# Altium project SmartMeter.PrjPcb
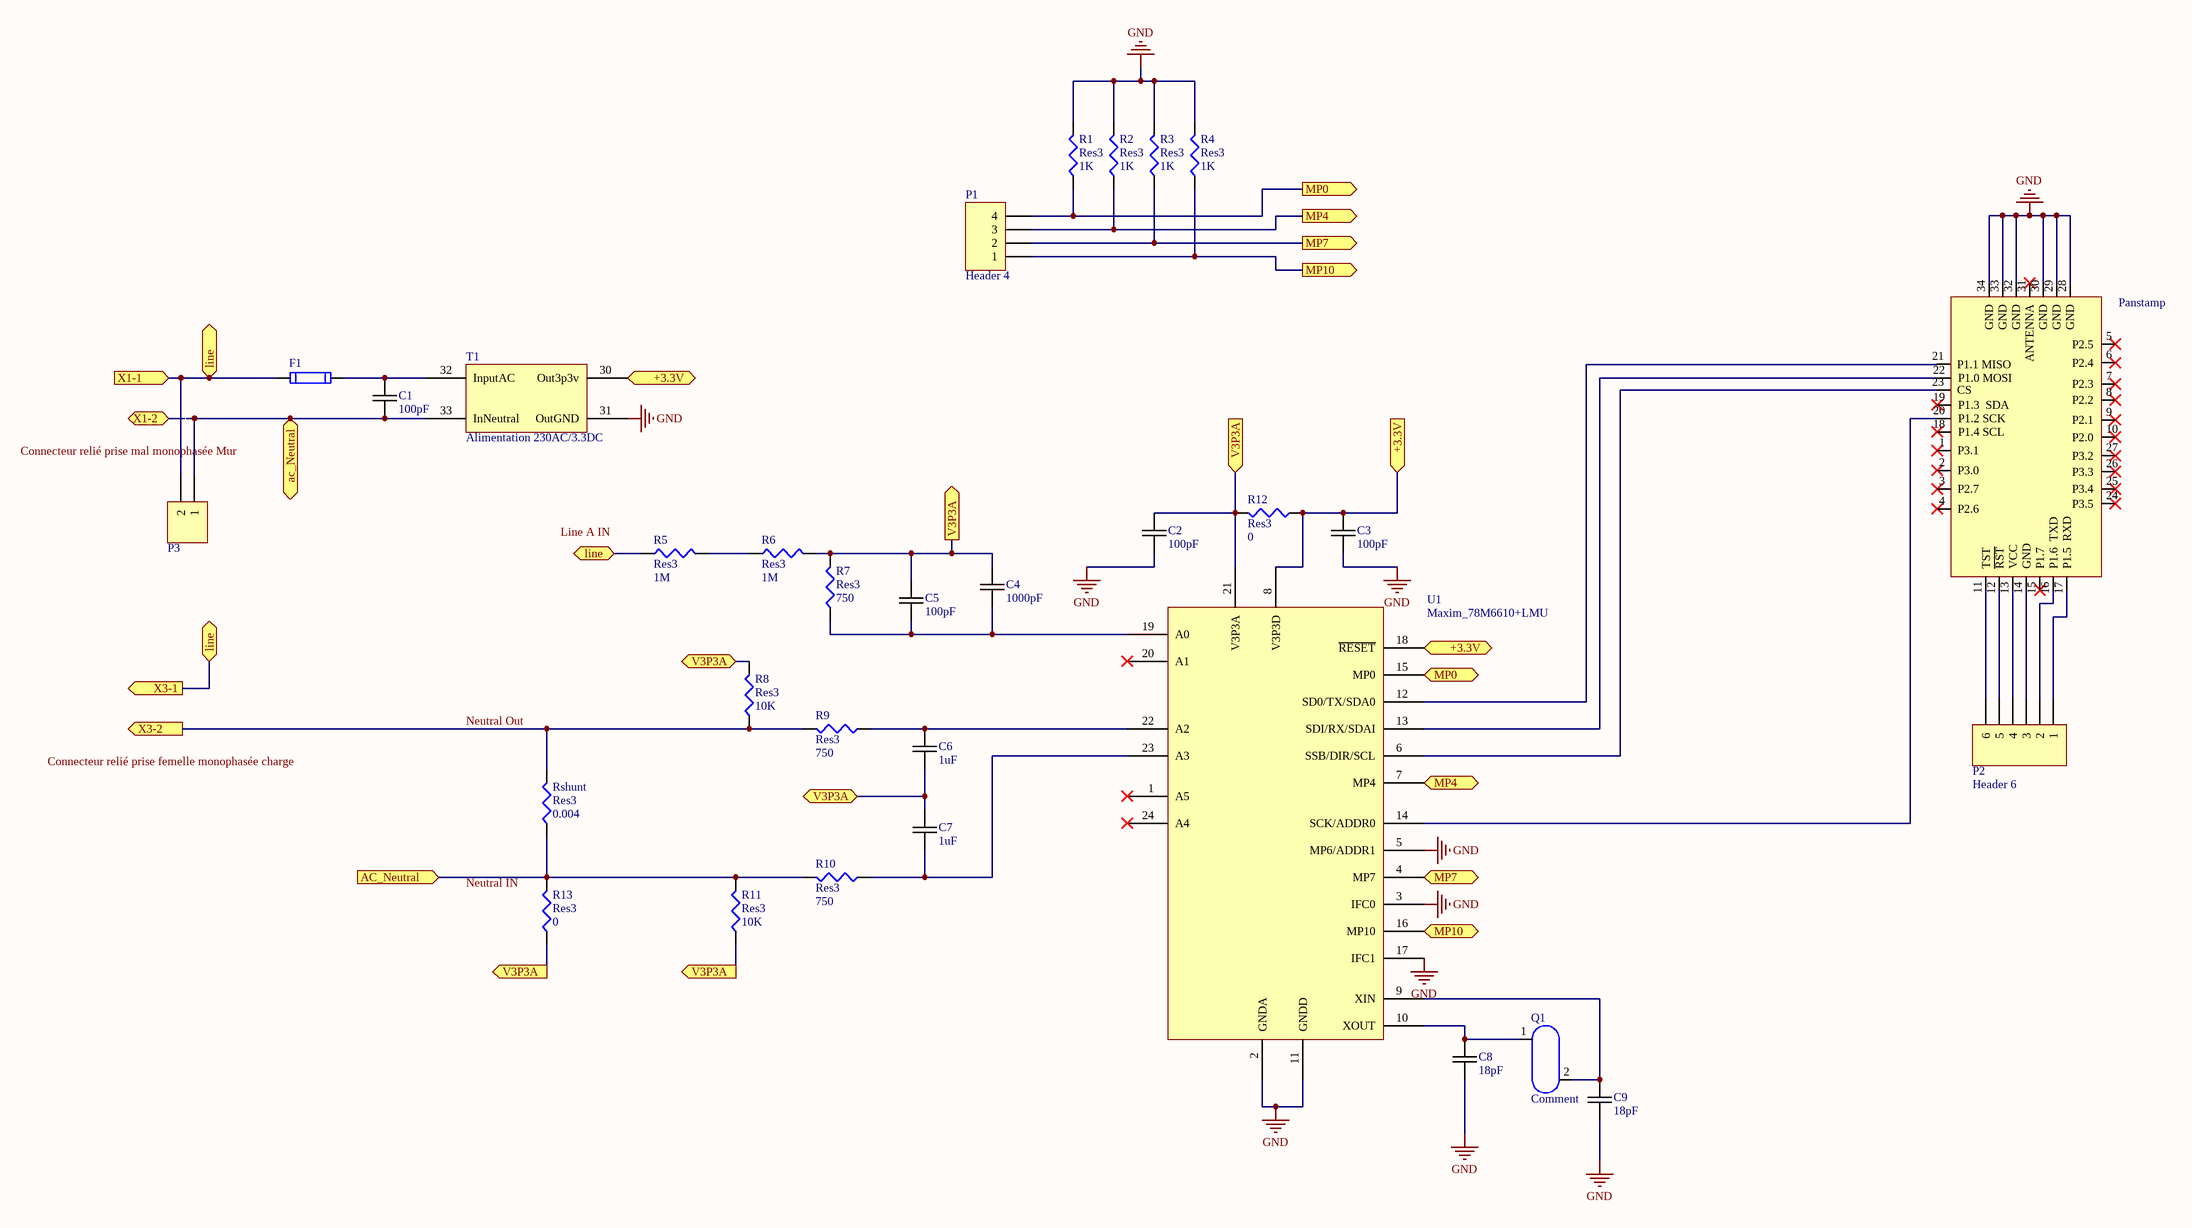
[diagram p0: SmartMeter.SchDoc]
1 sheet, 31 parts. Net scope: flat (ports and power ports of the same name join across sheets).
Board file: SmartMeter.PcbDoc

## Sheet SmartMeter.SchDoc
size A2

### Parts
C1  100pF  [WCAP-CSGP 0603, H=0.8mm]
C2  100pF  [WCAP-CSGP 0603, H=0.8mm]
C3  100pF  [WCAP-CSGP 0603, H=0.8mm]
C4  1000pF  [WCAP-CSGP 0603, H=0.8mm]
C5  100pF  [WCAP-CSGP 0603, H=0.8mm]
C6  1uF  [WCAP-CSGP 0603, H=0.8mm]
C7  1uF  [WCAP-CSGP 0603, H=0.8mm]
C8  18pF  [WCAP-CSGP 0603, H=0.8mm]
C9  18pF  [WCAP-CSGP 0603, H=0.8mm]
F1  696103201002  [696103201002]  (value not drawn)
P1  Header 4  [HDR1X4]
P2  Header 6  [HDR1X6]
P3  Header 2H  [HDR1X2H]  (value not drawn)
Panstamp  Panstamp  [PCBComponent_1]  (value not drawn)
Q1  Comment  [PCBComponent_1]
R1  Res3  value 1K  [J1-0603]
R2  Res3  value 1K  [J1-0603]
R3  Res3  value 1K  [J1-0603]
R4  Res3  value 1K  [J1-0603]
R5  Res3  value 1M  [J1-0603]
R6  Res3  value 1M  [J1-0603]
R7  Res3  value 750  [J1-0603]
R8  Res3  value 10K  [J1-0603]
R9  Res3  value 750  [J1-0603]
R10  Res3  value 750  [J1-0603]
R11  Res3  value 10K  [J1-0603]
R12  Res3  value 0  [J1-0603]
R13  Res3  value 0  [J1-0603]
Rshunt  Res3  value 0.004  [J1-0603]
T1  Alimentation 230AC/3.3DC  [PCBComponent_1]
U1  Maxim_78M6610+LMU  [21_0139I_T2444_4]

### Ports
+3.3V (in), +3.3V (out), ac_Neutral, AC_Neutral (in), line, MP0 (in), MP0 (out), MP4 (in), MP4 (out), MP7 (in), MP7 (out), MP10 (in), MP10 (out), V3P3A, V3P3A (in), V3P3A (out), X1-1 (in), X1-2, X3-1 (out), X3-2 (out)

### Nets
GND: C2.2 C3.2 C8.2 C9.2 Panstamp.28(GND) Panstamp.29(GND) Panstamp.30(GND) Panstamp.32(GND) Panstamp.33(GND) Panstamp.34(GND) R1.2 R2.2 R3.2 R4.2 T1.31(OutGND) U1.2(GNDA) U1.3(IFC0) U1.5(MP6/ADDR1) U1.11(GNDD) U1.17(IFC1)
Neutral Out: R8.1 R9.2 Rshunt.2 ; port X3-2
NetC1_1: C1.1 F1.2 T1.32(InputAC)
NetC1_2: C1.2 P3.1 R10.2 R11.2 R13.2 Rshunt.1 T1.33(InNeutral) ; port AC_Neutral, port ac_Neutral
NetC2_1: C2.1 C4.1 C5.1 C6.2 C7.1 R6.2 R7.2 R8.2 R11.1 R12.2 R13.1 U1.21(V3P3A) ; port V3P3A
NetC3_1: C3.1 R12.1 T1.30(Out3p3v) U1.8(V3P3D) U1.18(~{RESET}) ; port +3.3V
NetC4_2: C4.2 C5.2 R7.1 U1.19(A0)
NetC6_1: C6.1 R9.1 U1.22(A2)
NetC7_2: C7.2 R10.1 U1.23(A3)
NetC8_1: C8.1 Q1.1 U1.10(XOUT)
NetC9_1: C9.1 Q1.2 U1.9(XIN)
NetF1_1: F1.1 P3.2 R5.1 ; port X1-1, port X3-1, port line
NetP1_1: P1.1 R4.1 U1.16(MP10) ; port MP10
NetP1_2: P1.2 R3.1 U1.4(MP7) ; port MP7
NetP1_3: P1.3 R2.1 U1.7(MP4) ; port MP4
NetP1_4: P1.4 R1.1 U1.15(MP0) ; port MP0
NetP2_1: P2.1 Panstamp.17(P1.5__RXD)
NetP2_2: P2.2 Panstamp.16(P1.6__TXD)
NetP2_3: P2.3 Panstamp.14(GND)
NetP2_4: P2.4 Panstamp.13(VCC)
NetP2_5: P2.5 Panstamp.12(~{RST})
NetP2_6: P2.6 Panstamp.11(TST)
NetPanstamp_20: Panstamp.20(P1.2_SCK) U1.14(SCK/ADDR0)
NetPanstamp_21: Panstamp.21(P1.1_MISO) U1.12(SD0/TX/SDA0)
NetPanstamp_22: Panstamp.22(P1.0_MOSI) U1.13(SDI/RX/SDAI)
NetPanstamp_23: Panstamp.23(CS) U1.6(SSB/DIR/SCL)
NetR5_2: R5.2 R6.1

Not connected (* = marked no-connect by the designer): Panstamp 1(P3.1)* 2(P3.0)* 3(P2.7)* 4(P2.6)* 5(P2.5)* 6(P2.4)* 7(P2.3)* 8(P2.2)* 9(P2.1)* 10(P2.0)* 15(P1.7)* 18(P1.4_SCL)* 19(P1.3__SDA)* 24(P3.5)* 25(P3.4)* 26(P3.3)* 27(P3.2)* 31(ANTENNA)*; U1 1(A5)* 20(A1)* 24(A4)*

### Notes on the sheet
- Labels drawn without touching a wire or pin: Connecteur relié prise femelle monophasée charge, Connecteur relié prise mal monophasée Mur, Line A IN, Neutral IN

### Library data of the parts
C1-C9 = 0603C-1UF-10V-X5R-TDK: CAPACITOR 0603 CERAMIC; Manufacturer: TDK Corporation; Manufacturer Part Number: C1608X5R1A105K; Reel: C23
F1 = WR-FSH, 696103201002: WR-FSH Fuseholder THR Blocks PCB Clip Cover; Manufacturer: Wurth Elektronik; ComponentLink1 Description: Manufacturer; ComponentLink2 Description: Datasheet; NoPins: 2
P1 = Header 4: Header, 4-Pin
P2 = Header 6: Header, 6-Pin
P3 = Header 2H: Header, 2-Pin, Right Angle
Panstamp = Panstamp: Panstamp NRG 2.0
Q1 = Component_1
R1-R13 Rshunt = Res3: Resistor
U1 = Maxim78M6610 + LMU: Mesure d'énergie IC ENERGY MM PROCESSOR 24TQFN; Manufacturer: Maxim Integrated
